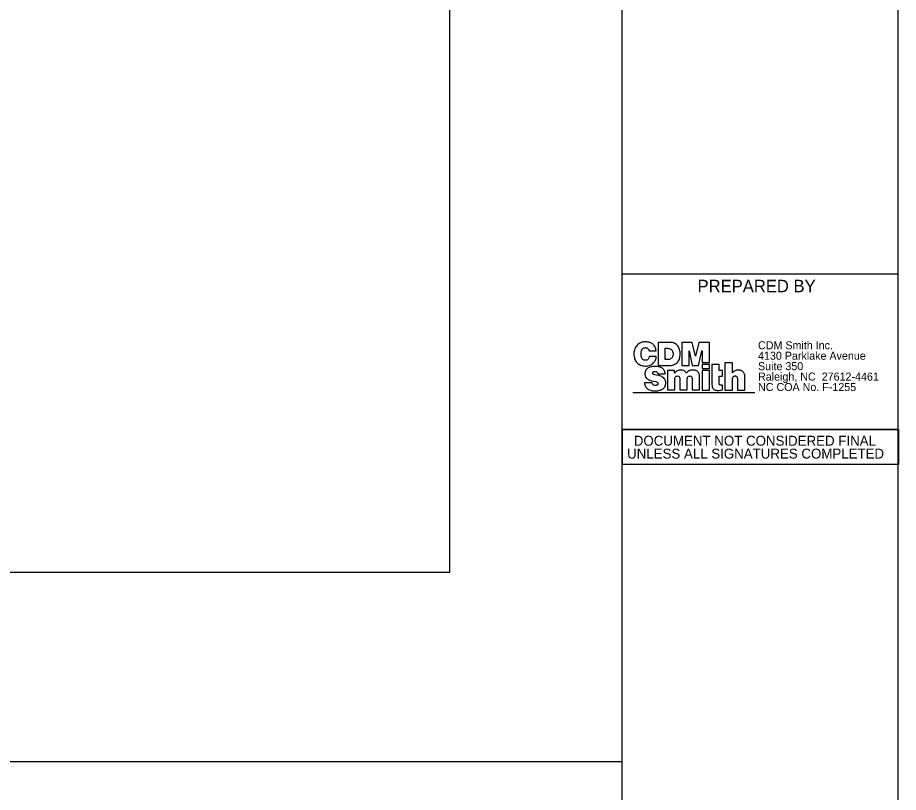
# Model space of a CAD drawing. Extents: x 24 to 2046, y 15 to 1115.
# Drawn here: x 1367.4 to 1686.5, y 554 to 834.5 of the extents above; entities that cross this region are included whole.
import ezdxf

# ---------------------------------------------------------------- set-up
doc = ezdxf.new("R2010")
doc.units = 0
for name, color, linetype in [('Sheet Block Title CELL', 7, 'Continuous'), ('Sheet_RDY_PE_Seal_Cell', 7, 'Continuous'), ('z - Construction', 7, 'Continuous')]:
    doc.layers.add(name, color=color, linetype=linetype)

msp = doc.modelspace()

# ---------------------------------------------------------------- linework, layer by layer
at = {"layer": 'Sheet Block Title CELL'}
msp.add_line((1590.3, 698.7), (1634.47, 698.7), dxfattribs=at)
for points in [[(1593.57, 711.15), (1593.49, 711.32), (1593.43, 711.49), (1593.32, 711.89), (1593.26, 712.28), (1593.23, 712.71), (1593.26, 713.14), (1593.32, 713.53), (1593.43, 713.93), (1593.49, 714.1), (1593.57, 714.27), (1593.69, 714.44), (1593.8, 714.59), (1593.91, 714.7), (1594.09, 714.81), (1594.23, 714.9), (1594.43, 714.96), (1594.62, 714.98), (1594.82, 715.01), (1595.02, 714.98), (1595.19, 714.96), (1595.34, 714.93), (1595.48, 714.87), (1595.62, 714.78), (1595.7, 714.7), (1595.88, 714.5), (1596.02, 714.3), (1596.1, 714.1), (1596.16, 713.9), (1596.19, 713.79), (1598.69, 713.79), (1598.63, 714.16), (1598.55, 714.53), (1598.46, 714.87), (1598.32, 715.18), (1598.18, 715.47), (1598.01, 715.75), (1597.81, 716.01), (1597.58, 716.21), (1597.32, 716.4), (1597.04, 716.6), (1596.76, 716.75), (1596.44, 716.86), (1596.07, 716.97), (1595.7, 717.03), (1595.31, 717.09), (1594.91, 717.09), (1594.43, 717.09), (1593.97, 717), (1593.55, 716.92), (1593.15, 716.77), (1592.78, 716.6), (1592.44, 716.4), (1592.1, 716.15), (1591.81, 715.89), (1591.56, 715.58), (1591.33, 715.27), (1591.13, 714.9), (1590.96, 714.5), (1590.82, 714.1), (1590.73, 713.65), (1590.68, 713.19), (1590.65, 712.71), (1590.68, 712.26), (1590.73, 711.8), (1590.82, 711.38), (1590.93, 710.98), (1591.1, 710.61), (1591.27, 710.24), (1591.5, 709.9), (1591.75, 709.59), (1592.04, 709.3), (1592.38, 709.07), (1592.72, 708.85), (1593.09, 708.68), (1593.49, 708.53), (1593.94, 708.42), (1594.4, 708.36), (1594.91, 708.33), (1595.34, 708.33), (1595.76, 708.42), (1596.16, 708.51), (1596.53, 708.65), (1596.87, 708.79), (1597.18, 708.99), (1597.47, 709.19), (1597.72, 709.44), (1597.95, 709.7), (1598.15, 709.95), (1598.32, 710.27), (1598.46, 710.55), (1598.57, 710.86), (1598.66, 711.18), (1598.72, 711.49), (1598.72, 711.8), (1596.19, 711.8), (1596.13, 711.52), (1596.05, 711.26), (1595.93, 711.03), (1595.79, 710.81), (1595.59, 710.64), (1595.39, 710.52), (1595.14, 710.44), (1594.82, 710.41), (1594.62, 710.44), (1594.43, 710.47), (1594.23, 710.52), (1594.08, 710.61), (1593.91, 710.72), (1593.8, 710.84), (1593.69, 710.98), (1593.57, 711.15)], [(1607.41, 712.26), (1607.41, 712.71), (1607.41, 713.11), (1607.38, 713.51), (1607.3, 713.9), (1607.21, 714.27), (1607.1, 714.61), (1606.96, 714.98), (1606.79, 715.3), (1606.59, 715.61), (1606.33, 715.89), (1606.08, 716.12), (1605.76, 716.35), (1605.42, 716.55), (1605.02, 716.69), (1604.6, 716.8), (1604.14, 716.86), (1603.63, 716.89), (1599.4, 716.89), (1599.4, 708.53), (1603.15, 708.53), (1603.66, 708.53), (1604.17, 708.59), (1604.63, 708.7), (1605.05, 708.82), (1605.42, 708.99), (1605.79, 709.19), (1606.1, 709.41), (1606.39, 709.67), (1606.62, 709.95), (1606.84, 710.27), (1607.01, 710.61), (1607.16, 710.98), (1607.27, 711.37), (1607.35, 711.8), (1607.41, 712.26)], [(1610.62, 713.9), (1610.68, 713.9), (1611.82, 708.53), (1614.09, 708.53), (1615.31, 713.9), (1615.37, 713.9), (1615.37, 709.58), (1618.01, 709.58), (1618.01, 716.89), (1614.2, 716.89), (1613.01, 711.97), (1612.98, 711.97), (1611.79, 716.89), (1608.01, 716.89), (1608.01, 708.53), (1610.62, 708.53), (1610.62, 713.9)], [(1601.98, 714.76), (1602.81, 714.76), (1603.15, 714.73), (1603.43, 714.7), (1603.69, 714.61), (1603.92, 714.5), (1604.12, 714.39), (1604.29, 714.24), (1604.4, 714.1), (1604.51, 713.96), (1604.63, 713.79), (1604.68, 713.62), (1604.8, 713.28), (1604.83, 712.99), (1604.85, 712.77), (1604.83, 712.45), (1604.77, 712.11), (1604.68, 711.74), (1604.6, 711.57), (1604.51, 711.43), (1604.43, 711.26), (1604.29, 711.12), (1604.14, 711.01), (1603.97, 710.89), (1603.77, 710.81), (1603.55, 710.72), (1603.29, 710.69), (1603.01, 710.66), (1601.98, 710.66), (1601.98, 714.76)], [(1618.01, 708.87), (1615.37, 708.87), (1615.37, 707.42), (1618.01, 707.42), (1618.01, 708.87)], [(1622.7, 706.71), (1621.53, 706.71), (1621.53, 708.87), (1618.92, 708.87), (1618.92, 706.71), (1618.92, 704.73), (1618.92, 702.25), (1618.92, 701.71), (1618.98, 701.23), (1619.06, 700.83), (1619.17, 700.49), (1619.32, 700.24), (1619.46, 700.04), (1619.66, 699.89), (1619.86, 699.75), (1620.11, 699.64), (1620.42, 699.55), (1620.79, 699.5), (1621.25, 699.5), (1621.56, 699.5), (1621.93, 699.55), (1622.33, 699.61), (1622.7, 699.72), (1622.7, 701.49), (1622.58, 701.46), (1622.39, 701.43), (1621.99, 701.4), (1621.85, 701.43), (1621.73, 701.51), (1621.67, 701.57), (1621.62, 701.63), (1621.59, 701.71), (1621.56, 701.86), (1621.53, 702.22), (1621.53, 704.73), (1622.7, 704.73), (1622.7, 706.71)], [(1630.74, 705.35), (1630.63, 705.61), (1630.54, 705.83), (1630.4, 706.03), (1630.26, 706.2), (1630.09, 706.37), (1629.92, 706.49), (1629.72, 706.6), (1629.49, 706.71), (1629.26, 706.77), (1629.03, 706.83), (1628.78, 706.86), (1628.52, 706.88), (1628.18, 706.86), (1627.87, 706.83), (1627.56, 706.77), (1627.22, 706.63), (1626.99, 706.49), (1626.79, 706.34), (1626.56, 706.15), (1626.33, 705.92), (1626.33, 709.5), (1623.61, 709.5), (1623.61, 699.64), (1626.33, 699.64), (1626.33, 703.05), (1626.33, 703.47), (1626.39, 703.87), (1626.51, 704.16), (1626.56, 704.27), (1626.62, 704.38), (1626.73, 704.53), (1626.9, 704.64), (1627.07, 704.73), (1627.24, 704.75), (1627.47, 704.75), (1627.64, 704.7), (1627.78, 704.61), (1627.93, 704.47), (1628.04, 704.33), (1628.1, 704.1), (1628.15, 703.84), (1628.15, 703.53), (1628.15, 699.64), (1630.88, 699.64), (1630.88, 704.13), (1630.88, 704.47), (1630.85, 704.78), (1630.8, 705.09), (1630.74, 705.35)], [(1602.18, 702.57), (1602.15, 702.79), (1602.1, 702.99), (1602.04, 703.22), (1601.96, 703.39), (1601.87, 703.56), (1601.76, 703.73), (1601.64, 703.87), (1601.36, 704.13), (1601.05, 704.36), (1600.73, 704.53), (1600.36, 704.67), (1599.99, 704.78), (1599.63, 704.87), (1598.89, 705.04), (1598.26, 705.15), (1598.01, 705.24), (1597.78, 705.32), (1597.66, 705.38), (1597.55, 705.46), (1597.47, 705.58), (1597.44, 705.75), (1597.47, 705.95), (1597.52, 706.09), (1597.61, 706.2), (1597.72, 706.29), (1597.86, 706.35), (1598.03, 706.37), (1598.35, 706.4), (1598.52, 706.37), (1598.69, 706.35), (1598.83, 706.26), (1598.97, 706.15), (1599.11, 706.03), (1599.23, 705.89), (1599.28, 705.72), (1599.31, 705.52), (1601.98, 705.52), (1601.96, 705.92), (1601.87, 706.26), (1601.76, 706.57), (1601.61, 706.86), (1601.42, 707.08), (1601.22, 707.31), (1600.99, 707.51), (1600.71, 707.65), (1600.45, 707.79), (1600.14, 707.91), (1599.85, 707.99), (1599.54, 708.08), (1599.2, 708.14), (1598.89, 708.16), (1598.26, 708.19), (1597.66, 708.16), (1597.35, 708.11), (1597.04, 708.08), (1596.73, 707.99), (1596.44, 707.91), (1596.16, 707.79), (1595.87, 707.65), (1595.62, 707.48), (1595.36, 707.28), (1595.16, 707.06), (1594.99, 706.83), (1594.85, 706.54), (1594.74, 706.23), (1594.65, 705.89), (1594.62, 705.49), (1594.65, 705.24), (1594.68, 704.98), (1594.74, 704.75), (1594.82, 704.53), (1594.91, 704.33), (1595.05, 704.13), (1595.19, 703.96), (1595.36, 703.79), (1595.56, 703.65), (1595.79, 703.5), (1596.05, 703.36), (1596.33, 703.25), (1596.64, 703.13), (1596.98, 703.02), (1597.78, 702.85), (1598.6, 702.68), (1598.89, 702.59), (1599.09, 702.51), (1599.23, 702.4), (1599.31, 702.28), (1599.37, 702.14), (1599.4, 701.97), (1599.37, 701.8), (1599.28, 701.66), (1599.17, 701.54), (1599.03, 701.46), (1598.89, 701.4), (1598.72, 701.34), (1598.4, 701.32), (1598.15, 701.34), (1597.92, 701.37), (1597.75, 701.46), (1597.61, 701.54), (1597.47, 701.71), (1597.35, 701.91), (1597.3, 702.08), (1597.27, 702.31), (1594.45, 702.31), (1594.48, 701.91), (1594.57, 701.54), (1594.68, 701.23), (1594.82, 700.92), (1594.99, 700.66), (1595.22, 700.41), (1595.45, 700.18), (1595.7, 700.01), (1595.99, 699.84), (1596.3, 699.7), (1596.61, 699.58), (1596.93, 699.5), (1597.27, 699.41), (1597.61, 699.38), (1597.95, 699.36), (1598.29, 699.33), (1599, 699.36), (1599.34, 699.41), (1599.68, 699.47), (1600.02, 699.55), (1600.34, 699.67), (1600.65, 699.78), (1600.93, 699.95), (1601.22, 700.12), (1601.44, 700.35), (1601.67, 700.58), (1601.84, 700.86), (1601.98, 701.17), (1602.1, 701.52), (1602.18, 701.88), (1602.18, 702.31), (1602.18, 702.57)], [(1605.54, 703.99), (1605.59, 704.19), (1605.71, 704.38), (1605.82, 704.53), (1605.96, 704.64), (1606.16, 704.73), (1606.42, 704.75), (1606.67, 704.73), (1606.9, 704.64), (1607.04, 704.53), (1607.16, 704.36), (1607.21, 704.16), (1607.27, 703.96), (1607.3, 703.73), (1607.3, 703.48), (1607.3, 699.67), (1609.97, 699.67), (1609.97, 703.48), (1610, 703.73), (1610.03, 703.99), (1610.08, 704.19), (1610.2, 704.38), (1610.31, 704.53), (1610.45, 704.64), (1610.65, 704.73), (1610.91, 704.75), (1611.16, 704.73), (1611.39, 704.64), (1611.53, 704.53), (1611.64, 704.36), (1611.7, 704.16), (1611.76, 703.96), (1611.79, 703.73), (1611.79, 703.48), (1611.79, 699.67), (1614.46, 699.67), (1614.46, 704.5), (1614.43, 704.92), (1614.4, 705.15), (1614.34, 705.35), (1614.29, 705.55), (1614.17, 705.75), (1614.06, 705.95), (1613.95, 706.12), (1613.78, 706.29), (1613.61, 706.43), (1613.41, 706.57), (1613.18, 706.69), (1612.95, 706.77), (1612.67, 706.83), (1612.38, 706.89), (1612.04, 706.89), (1611.73, 706.89), (1611.45, 706.86), (1611.19, 706.8), (1610.93, 706.74), (1610.74, 706.66), (1610.54, 706.57), (1610.22, 706.37), (1610, 706.17), (1609.83, 706), (1609.66, 705.78), (1609.49, 706.03), (1609.31, 706.26), (1609.09, 706.46), (1608.86, 706.6), (1608.58, 706.71), (1608.32, 706.83), (1608.04, 706.89), (1607.72, 706.89), (1607.38, 706.89), (1607.04, 706.83), (1606.73, 706.74), (1606.42, 706.63), (1606.13, 706.49), (1605.88, 706.29), (1605.65, 706.06), (1605.39, 705.74), (1605.39, 706.71), (1602.81, 706.71), (1602.81, 699.67), (1605.48, 699.67), (1605.48, 703.48), (1605.51, 703.73), (1605.54, 703.99)], [(1618.01, 706.71), (1615.37, 706.71), (1615.37, 699.64), (1618.01, 699.64), (1618.01, 706.71)]]:
    msp.add_lwpolyline(points, dxfattribs=at)
at = {"layer": 'Sheet_RDY_PE_Seal_Cell'}
msp.add_lwpolyline([(123.95, 633.73), (1523.94, 633.73), (1523.94, 1008.73), (123.95, 1008.73)], close=True, dxfattribs=at)
at = {"layer": 'z - Construction'}
for p, q in [((1586.43, 52.48), (1586.45, 1077.48)), ((1686.43, 52.48), (1686.45, 1077.48)), ((1686.42, 741.61), (1586.43, 741.61)), ((1686.48, 685.42), (1586.48, 685.42)), ((1586.44, 564.98), (61.45, 564.98))]:
    msp.add_line(p, q, dxfattribs=at)
msp.add_lwpolyline([(1586.48, 685.42), (1686.48, 685.42), (1686.48, 672.68), (1586.48, 672.68)], close=True, dxfattribs=at)

# ---------------------------------------------------------------- texts
at = {"layer": 'Sheet Block Title CELL'}
for s, height, p in [('CDM Smith Inc.', 2.9003, (1635.63, 714.4)), ('4130 Parklake Avenue', 2.9003, (1635.63, 710.62)), ('Suite 350', 2.9, (1635.63, 706.84)), ('Raleigh, NC  27612-4461', 2.9003, (1635.63, 703.07)), ('NC COA No. F-1255', 2.9003, (1635.63, 699.29))]:
    msp.add_text(s, height=height, rotation=359.9982, dxfattribs=at).set_placement(p)
at = {"layer": 'z - Construction'}
for s, height, p in [('PREPARED BY', 4.5, (1613.71, 735.06)), ('DOCUMENT NOT CONSIDERED FINAL', 3.6, (1590.63, 679.49)), ('UNLESS ALL SIGNATURES COMPLETED', 3.6, (1588.2, 674.83))]:
    msp.add_text(s, height=height, rotation=0, dxfattribs=at).set_placement(p)

doc.saveas('drawing.dxf')
